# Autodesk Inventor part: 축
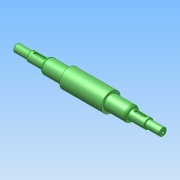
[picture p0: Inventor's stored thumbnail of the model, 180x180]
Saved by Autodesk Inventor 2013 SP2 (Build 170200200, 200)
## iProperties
Created: 2025-10
Part Number: 축
Material: Generic
Document SubType Name: Modeling
Designer: a
Density: 1 g/cm^3
Author: a
변환 표준: STEP AP214IS
전처리기: Build: 200, Release: 2013 SP2 Update 6 - Date: Thu 07/17/2014
전송 단위: 밀리미터
불확실성: 0.01
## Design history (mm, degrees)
node "축1"
node "솔리드1"
node "기준1"
